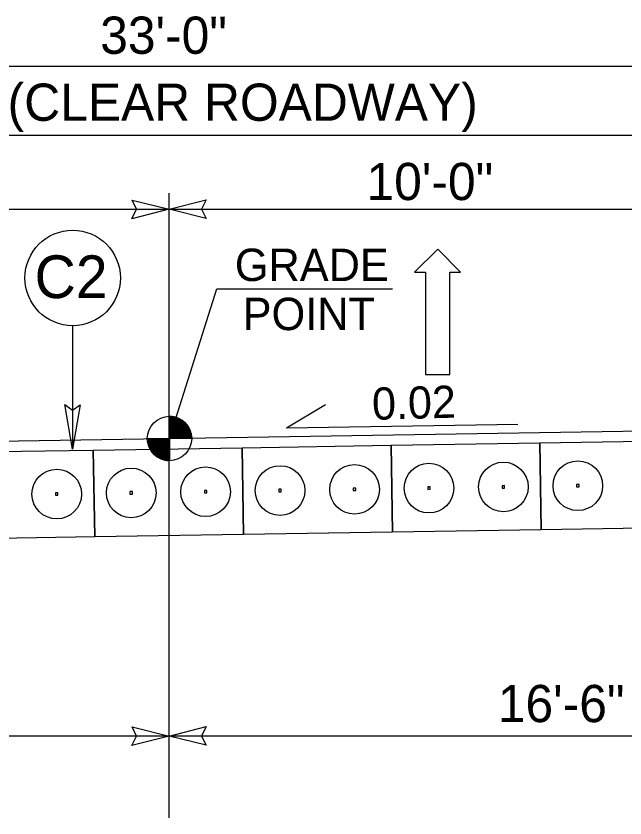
# Model space of a CAD drawing. Extents: x 573980 to 574178, y -53449 to -53334.
# Drawn here: x 574085.55 to 574100.88, y -53436.63 to -53416.43 of the extents above; entities that cross this region are included whole.
import ezdxf

# ---------------------------------------------------------------- set-up
doc = ezdxf.new("R2010")
doc.units = 0
for name, color, linetype in [('Old_Level_1', 7, 'Continuous'), ('Old_Level_11', 7, 'Continuous'), ('Old_Level_2', 7, 'Continuous'), ('Prop Dimension Text', 7, 'Continuous'), ('Prop Lane Arrow CELL', 7, 'Continuous'), ('Typical Arrow Superelevation CELL', 7, 'Continuous'), ('Typical Berm Information CELL', 7, 'Continuous'), ('Typical Grade Point Symbol CELL', 7, 'Continuous'), ('Typical ID Circle CELL', 7, 'Continuous'), ('Typical Terminator CELL', 7, 'Continuous'), ('Typical Text Grade Point CELL', 7, 'Continuous'), ('Typical Text ID Circle CELL', 7, 'Continuous')]:
    doc.layers.add(name, color=color, linetype=linetype)

# ---------------------------------------------------------------- blocks, each defined once
blk = doc.blocks.new('TERMINATOR')
at = {"layer": 'Typical Terminator CELL'}
blk.add_lwpolyline([(-0.4687, 0.0807), (0, 0), (-0.4713, -0.0833), (-0.4114, 0)], close=True, dxfattribs=at)
blk = doc.blocks.new('Lane Arrow Through')
at = {"layer": 'Prop Lane Arrow CELL'}
for p, q in [((-3.15, 1.6), (-3.15, 3.1)), ((-3.15, 3.1), (0, 0)), ((-17.15, 1.6), (-3.15, 1.6)), ((-17.15, -1.7), (-17.15, 1.6)), ((0, 0), (-3.15, -3.2)), ((-3.15, -1.7), (-17.15, -1.7)), ((-3.15, -3.2), (-3.15, -1.7))]:
    blk.add_line(p, q, dxfattribs=at)

msp = doc.modelspace()

# ---------------------------------------------------------------- linework, layer by layer
at = {"layer": 'Old_Level_1'}
for p, q in [((574070.29, -53427.378), (574108.44, -53426.767)), ((574098.743, -53427.183), (574102.493, -53427.123)), ((574087.495, -53427.363), (574091.244, -53427.303)), ((574091.244, -53427.303), (574094.994, -53427.243)), ((574091.244, -53427.303), (574091.279, -53429.49)), ((574091.279, -53429.49), (574091.244, -53427.303)), ((574094.994, -53427.243), (574098.743, -53427.183)), ((574094.994, -53427.243), (574095.029, -53429.43)), ((574095.029, -53429.43), (574094.994, -53427.243)), ((574098.743, -53427.183), (574098.778, -53429.37)), ((574098.778, -53429.37), (574098.743, -53427.183)), ((574083.745, -53427.423), (574087.495, -53427.363)), ((574087.495, -53427.363), (574087.53, -53429.55)), ((574087.53, -53429.55), (574087.495, -53427.363)), ((574092.199, -53428.35), (574092.167, -53428.35)), ((574092.167, -53428.35), (574092.168, -53428.412)), ((574092.229, -53428.349), (574092.199, -53428.35)), ((574092.229, -53428.411), (574092.229, -53428.349)), ((574094.073, -53428.32), (574094.041, -53428.32)), ((574094.041, -53428.32), (574094.042, -53428.382)), ((574094.103, -53428.319), (574094.073, -53428.32)), ((574094.104, -53428.381), (574094.103, -53428.319)), ((574095.948, -53428.29), (574095.916, -53428.29)), ((574095.916, -53428.29), (574095.917, -53428.352)), ((574095.917, -53428.352), (574095.979, -53428.351)), ((574095.978, -53428.289), (574095.948, -53428.29)), ((574095.979, -53428.351), (574095.978, -53428.289)), ((574097.823, -53428.26), (574097.791, -53428.26)), ((574097.791, -53428.26), (574097.792, -53428.322)), ((574097.792, -53428.322), (574097.854, -53428.321)), ((574097.853, -53428.259), (574097.823, -53428.26)), ((574097.854, -53428.321), (574097.853, -53428.259)), ((574099.698, -53428.23), (574099.666, -53428.23)), ((574099.666, -53428.23), (574099.667, -53428.292)), ((574099.667, -53428.292), (574099.729, -53428.291)), ((574099.728, -53428.229), (574099.698, -53428.23)), ((574099.729, -53428.291), (574099.728, -53428.229)), ((574086.574, -53428.44), (574086.542, -53428.44)), ((574086.542, -53428.44), (574086.543, -53428.502)), ((574086.543, -53428.502), (574086.605, -53428.501)), ((574086.604, -53428.439), (574086.574, -53428.44)), ((574086.605, -53428.501), (574086.604, -53428.439)), ((574088.449, -53428.41), (574088.417, -53428.41)), ((574088.417, -53428.41), (574088.418, -53428.472)), ((574088.418, -53428.472), (574088.48, -53428.471)), ((574088.479, -53428.409), (574088.449, -53428.41)), ((574088.48, -53428.471), (574088.479, -53428.409)), ((574090.324, -53428.38), (574090.292, -53428.38)), ((574090.292, -53428.38), (574090.293, -53428.442)), ((574090.293, -53428.442), (574090.355, -53428.441)), ((574090.354, -53428.379), (574090.324, -53428.38)), ((574090.355, -53428.441), (574090.354, -53428.379)), ((574092.168, -53428.412), (574092.229, -53428.411)), ((574094.042, -53428.382), (574094.104, -53428.381)), ((574102.528, -53429.31), (574098.778, -53429.37)), ((574087.53, -53429.55), (574083.78, -53429.61)), ((574091.279, -53429.49), (574087.53, -53429.55)), ((574095.029, -53429.43), (574091.279, -53429.49)), ((574098.778, -53429.37), (574095.029, -53429.43))]:
    msp.add_line(p, q, dxfattribs=at)
for centre in [(574094.074, -53428.352), (574095.949, -53428.322), (574097.823, -53428.292), (574099.698, -53428.262), (574086.575, -53428.472), (574088.45, -53428.442), (574090.324, -53428.412), (574092.199, -53428.382)]:
    msp.add_circle(centre, 0.625, dxfattribs=at)
at = {"layer": 'Old_Level_2'}
msp.add_line((574089.403, -53436.626), (574089.403, -53420.895), dxfattribs=at)
at = {"layer": 'Prop Dimension Text'}
for p, q in [((574068.782, -53417.697), (574110.032, -53417.697)), ((574070.33, -53419.434), (574108.485, -53419.434)), ((574070.33, -53421.299), (574108.485, -53421.299)), ((574089.403, -53434.565), (574068.782, -53434.565)), ((574110.027, -53434.565), (574089.403, -53434.565))]:
    msp.add_line(p, q, dxfattribs=at)
at = {"layer": 'Typical Arrow Superelevation CELL'}
for q in [(574093.342, -53426.219), (574098.187, -53426.713)]:
    msp.add_line((574092.361, -53426.807), q, dxfattribs=at)
at = {"layer": 'Typical Grade Point Symbol CELL'}
for p, q in [((574089.414, -53427.072), (574090.604, -53423.302)), ((574089.414, -53427.072), (574089.417, -53426.512)), ((574088.855, -53427.07), (574089.414, -53427.072)), ((574089.411, -53427.631), (574089.414, -53427.072)), ((574089.414, -53427.072), (574089.411, -53427.631)), ((574089.974, -53427.074), (574089.414, -53427.072))]:
    msp.add_line(p, q, dxfattribs=at)
for points in [[(574089.422, -53426.512), (574089.422, -53426.512), (574089.419, -53427.072)], [(574089.433, -53426.512), (574089.431, -53427.072)], [(574089.444, -53426.514), (574089.442, -53427.072)], [(574089.455, -53426.514), (574089.453, -53427.072)], [(574089.466, -53426.515), (574089.464, -53427.072)], [(574089.477, -53426.516), (574089.475, -53427.072)], [(574089.489, -53426.518), (574089.486, -53427.072)], [(574089.5, -53426.519), (574089.498, -53427.072)], [(574089.511, -53426.52), (574089.509, -53427.072)], [(574089.522, -53426.523), (574089.52, -53427.072)], [(574089.533, -53426.525), (574089.531, -53427.072)], [(574089.545, -53426.528), (574089.542, -53427.072)], [(574089.556, -53426.53), (574089.554, -53427.072)], [(574089.567, -53426.534), (574089.565, -53427.072)], [(574089.578, -53426.537), (574089.576, -53427.073)], [(574089.589, -53426.54), (574089.587, -53427.073)], [(574089.6, -53426.544), (574089.598, -53427.073)], [(574089.612, -53426.548), (574089.61, -53427.073)], [(574089.623, -53426.553), (574089.621, -53427.073)], [(574089.634, -53426.558), (574089.632, -53427.073)], [(574089.645, -53426.563), (574089.643, -53427.073)], [(574089.656, -53426.568), (574089.654, -53427.073)], [(574089.667, -53426.573), (574089.665, -53427.073)], [(574089.679, -53426.579), (574089.677, -53427.073)], [(574089.69, -53426.586), (574089.688, -53427.073)], [(574089.701, -53426.592), (574089.699, -53427.073)], [(574089.712, -53426.598), (574089.71, -53427.073)], [(574089.723, -53426.606), (574089.721, -53427.073)], [(574089.734, -53426.613), (574089.733, -53427.073)], [(574089.746, -53426.622), (574089.744, -53427.073)], [(574089.757, -53426.629), (574089.755, -53427.073)], [(574089.768, -53426.638), (574089.766, -53427.073)], [(574089.779, -53426.648), (574089.777, -53427.073)], [(574089.79, -53426.658), (574089.789, -53427.073)], [(574089.801, -53426.668), (574089.8, -53427.073)], [(574089.812, -53426.679), (574089.811, -53427.073)], [(574089.824, -53426.691), (574089.822, -53427.074)], [(574089.835, -53426.703), (574089.833, -53427.074)], [(574089.846, -53426.717), (574089.845, -53427.074)], [(574089.857, -53426.73), (574089.856, -53427.074)], [(574089.868, -53426.745), (574089.867, -53427.074)], [(574089.879, -53426.762), (574089.878, -53427.074)], [(574089.89, -53426.779), (574089.889, -53427.074)], [(574089.902, -53426.798), (574089.9, -53427.074)], [(574089.913, -53426.818), (574089.912, -53427.074)], [(574089.924, -53426.841), (574089.923, -53427.074)], [(574089.935, -53426.868), (574089.934, -53427.074)], [(574089.946, -53426.899), (574089.945, -53427.074)], [(574089.957, -53426.937), (574089.956, -53427.074)], [(574088.857, -53427.07), (574088.857, -53427.131)], [(574088.868, -53427.07), (574088.868, -53427.197)], [(574088.88, -53427.07), (574088.879, -53427.236)], [(574088.891, -53427.07), (574088.89, -53427.27)], [(574088.902, -53427.07), (574088.901, -53427.296)], [(574088.913, -53427.07), (574088.912, -53427.32)], [(574088.924, -53427.07), (574088.923, -53427.341)], [(574088.936, -53427.07), (574088.935, -53427.361)], [(574088.947, -53427.07), (574088.946, -53427.378)], [(574088.958, -53427.07), (574088.957, -53427.395)], [(574088.969, -53427.07), (574088.968, -53427.41)], [(574088.98, -53427.07), (574088.979, -53427.423)], [(574088.992, -53427.07), (574088.99, -53427.437)], [(574089.003, -53427.07), (574089.001, -53427.449)], [(574089.014, -53427.07), (574089.012, -53427.462)], [(574089.025, -53427.07), (574089.024, -53427.473)], [(574089.036, -53427.07), (574089.035, -53427.483)], [(574089.048, -53427.07), (574089.046, -53427.493)], [(574089.059, -53427.07), (574089.057, -53427.503)], [(574089.07, -53427.071), (574089.068, -53427.512)], [(574089.081, -53427.071), (574089.079, -53427.521)], [(574089.092, -53427.071), (574089.09, -53427.528)], [(574089.103, -53427.071), (574089.102, -53427.536)], [(574089.115, -53427.071), (574089.113, -53427.543)], [(574089.126, -53427.071), (574089.124, -53427.551)], [(574089.137, -53427.071), (574089.135, -53427.557)], [(574089.148, -53427.071), (574089.146, -53427.563)], [(574089.159, -53427.071), (574089.157, -53427.569)], [(574089.171, -53427.071), (574089.169, -53427.574)], [(574089.182, -53427.071), (574089.18, -53427.579)], [(574089.193, -53427.071), (574089.191, -53427.584)], [(574089.204, -53427.071), (574089.202, -53427.589)], [(574089.215, -53427.071), (574089.213, -53427.595)], [(574089.227, -53427.071), (574089.224, -53427.598)], [(574089.238, -53427.071), (574089.236, -53427.602)], [(574089.249, -53427.071), (574089.247, -53427.606)], [(574089.26, -53427.071), (574089.258, -53427.608)], [(574089.271, -53427.071), (574089.269, -53427.612)], [(574089.283, -53427.071), (574089.28, -53427.615)], [(574089.294, -53427.071), (574089.292, -53427.617)], [(574089.305, -53427.071), (574089.303, -53427.62)], [(574089.316, -53427.072), (574089.314, -53427.622)], [(574089.327, -53427.072), (574089.325, -53427.624)], [(574089.338, -53427.072), (574089.336, -53427.626)], [(574089.35, -53427.072), (574089.347, -53427.627)], [(574089.361, -53427.072), (574089.359, -53427.629)], [(574089.372, -53427.072), (574089.37, -53427.63)], [(574089.383, -53427.072), (574089.381, -53427.63)], [(574089.394, -53427.072), (574089.392, -53427.631)], [(574089.406, -53427.072), (574089.403, -53427.631), (574089.403, -53427.631)], [(574089.968, -53426.994), (574089.968, -53427.074)]]:
    msp.add_lwpolyline(points, dxfattribs=at)
msp.add_circle((574089.414, -53427.072), 0.559, dxfattribs=at)
for start, end in [(359.7614, 89.7614), (179.7614, 269.7614)]:
    msp.add_arc((574089.414, -53427.072), 0.559, start, end, dxfattribs=at)
at = {"layer": 'Typical ID Circle CELL'}
msp.add_line((574086.975, -53424.231), (574086.975, -53427.337), dxfattribs=at)
msp.add_circle((574086.975, -53423.029), 1.202, dxfattribs=at)
at = {"layer": 'Typical Terminator CELL'}
msp.add_lwpolyline([(574087.166, -53426.224), (574086.975, -53427.337), (574086.777, -53426.218), (574086.975, -53426.36)], close=True, dxfattribs=at)
at = {"layer": 'Typical Text Grade Point CELL'}
msp.add_line((574090.604, -53423.302), (574095.027, -53423.302), dxfattribs=at)

# ---------------------------------------------------------------- block references
at = {"layer": 'Old_Level_1', "xscale": 0.18374999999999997, "yscale": -0.18374999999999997, "rotation": 89.99999999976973}
msp.add_blockref('Lane Arrow Through', (574096.176, -53422.306), dxfattribs=at)
at = {"layer": 'Old_Level_11', "xscale": 1.9883351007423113, "yscale": 2.8538812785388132}
for p, rotation in [((574089.403, -53421.299), -2.3029191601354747e-10), ((574089.403, -53421.299), 179.9999999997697), ((574089.403, -53434.565), -2.3029191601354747e-10), ((574089.403, -53434.565), 179.9999999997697)]:
    msp.add_blockref('TERMINATOR', p, dxfattribs=dict(at, rotation=rotation))

# ---------------------------------------------------------------- texts
at = {"layer": 'Prop Dimension Text'}
for s, p in [('33\'-0"', (574087.668, -53417.386)), ('30\'-6" (CLEAR ROADWAY)', (574081.795, -53419.073)), ('10\'-0"', (574094.375, -53421.069)), ('16\'-6"', (574097.682, -53434.214))]:
    msp.add_text(s, height=0.9375, rotation=360, dxfattribs=at).set_placement(p)
at = {"layer": 'Typical Berm Information CELL'}
msp.add_text('0.02', height=0.8113, rotation=1.5793, dxfattribs=at).set_placement((574094.526, -53426.604))
at = {"layer": 'Typical Text Grade Point CELL'}
for s, p in [('GRADE', (574091.059, -53423.107)), ('POINT', (574091.256, -53424.343))]:
    msp.add_text(s, height=0.8156, rotation=360, dxfattribs=at).set_placement(p)
at = {"layer": 'Typical Text ID Circle CELL'}
msp.add_text('C2', height=1.076, dxfattribs=at).set_placement((574086.016, -53423.537))

doc.saveas('drawing.dxf')
